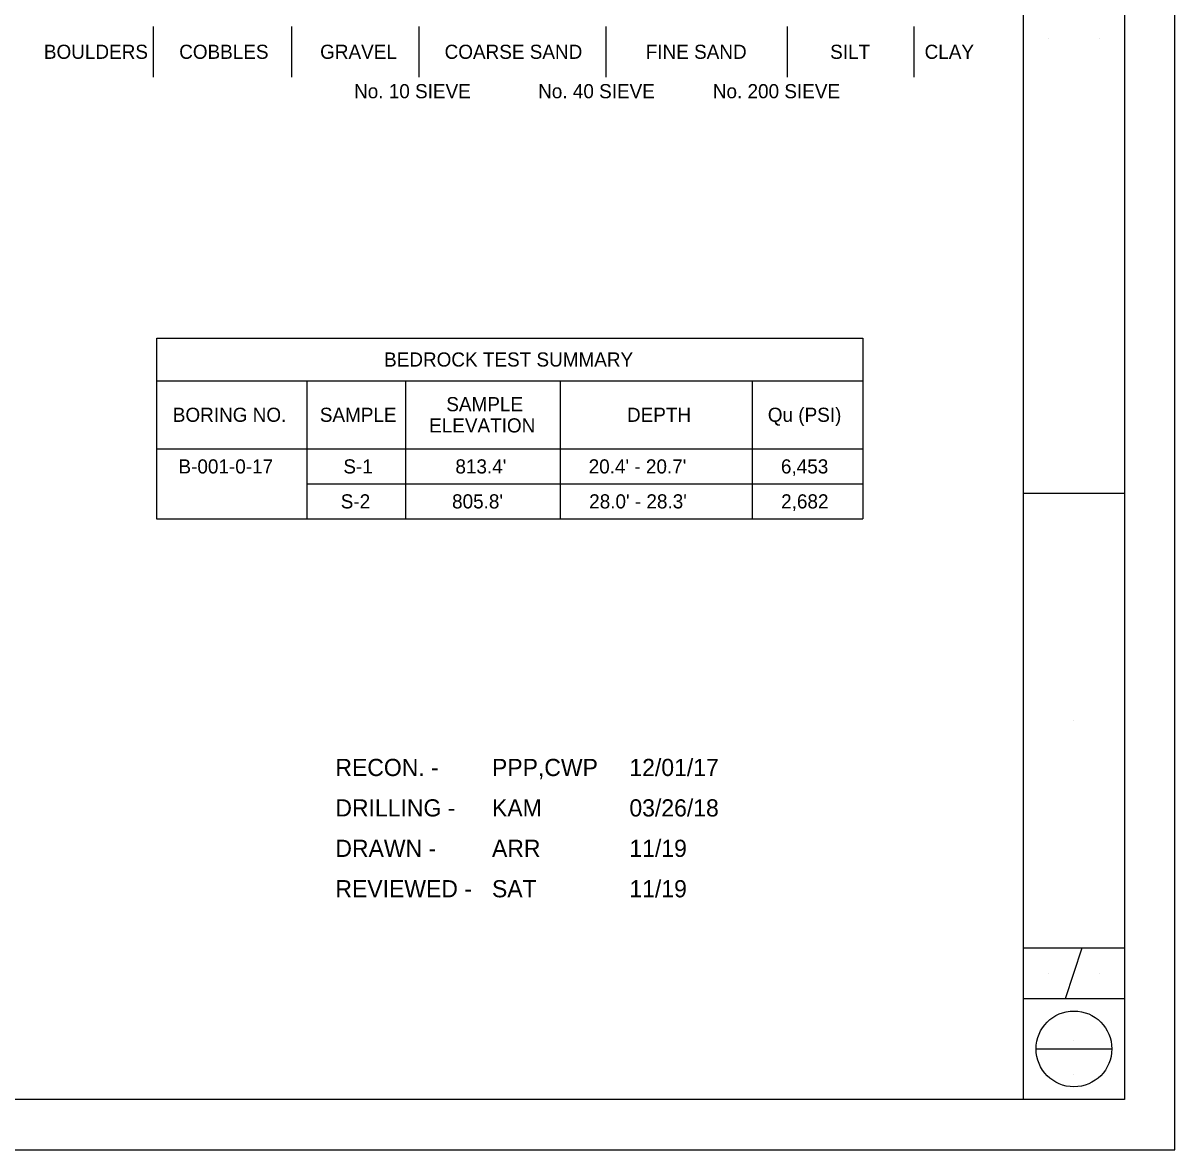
# Model space of a CAD drawing. Extents: x 0 to 34, y 0 to 22.
# Drawn here: x 22.6 to 34, y 0 to 11.15 of the extents above; entities that cross this region are included whole.
import ezdxf

# ---------------------------------------------------------------- set-up
doc = ezdxf.new("R2010")
doc.units = 0
for name, color, linetype in [('SH_Border', 7, 'Continuous'), ('SH_Cut_Line', 7, 'Continuous'), ('SH_Data', 7, 'Continuous'), ('SH_Text', 7, 'Continuous')]:
    doc.layers.add(name, color=color, linetype=linetype)

msp = doc.modelspace()

# ---------------------------------------------------------------- linework, layer by layer
at = {"layer": 'SH_Border'}
for p, q in [((32.5, 0.5), (32.5, 21.5)), ((32.5, 6.5), (33.5, 6.5)), ((32.5, 2), (33.5, 2)), ((32.917, 1.5), (33.083, 2)), ((32.5, 1.5), (33.5, 1.5))]:
    msp.add_line(p, q, dxfattribs=at)
msp.add_lwpolyline([(2, 21.5), (33.5, 21.5), (33.5, 0.5), (2, 0.5)], close=True, dxfattribs=at)
at = {"layer": 'SH_Cut_Line'}
msp.add_lwpolyline([(0, 0), (34, 0), (34, 22), (0, 22)], close=True, dxfattribs=at)
at = {"layer": 'SH_Data'}
for p, q in [((32.75, 11), (32.75, 11)), ((33.25, 11), (33.25, 11)), ((23.921, 8.032), (23.921, 6.245)), ((23.922, 8.032), (30.911, 8.032)), ((30.911, 8.032), (30.911, 6.245)), ((23.922, 7.612), (30.911, 7.612)), ((25.411, 6.245), (25.411, 7.612)), ((26.387, 6.245), (26.387, 7.612)), ((27.917, 6.245), (27.917, 7.612)), ((29.82, 6.245), (29.82, 7.612)), ((23.922, 6.937), (30.911, 6.937)), ((25.411, 6.591), (30.911, 6.591)), ((23.919, 6.245), (30.911, 6.245)), ((33, 4.25), (33, 4.25)), ((32.75, 1.75), (32.75, 1.75)), ((33.25, 1.75), (33.25, 1.75)), ((33, 1.085), (33, 1.085)), ((32.625, 1), (33.375, 1)), ((33, 0.745), (33, 0.745))]:
    msp.add_line(p, q, dxfattribs=at)
msp.add_circle((33, 1), 0.375, dxfattribs=at)
at = {"layer": 'SH_Text'}
for p, q in [((23.89, 10.617), (23.89, 11.117)), ((25.26, 10.617), (25.26, 11.117)), ((26.52, 10.617), (26.52, 11.117)), ((28.37, 10.617), (28.37, 11.117)), ((30.165, 10.617), (30.165, 11.117)), ((31.419, 10.617), (31.419, 11.117))]:
    msp.add_line(p, q, dxfattribs=at)

# ---------------------------------------------------------------- texts
for s, height, p in [('BOULDERS', 0.14, (22.805, 10.797)), ('COBBLES', 0.14, (24.144, 10.797)), ('GRAVEL', 0.14, (25.539, 10.797)), ('COARSE SAND', 0.14, (26.771, 10.797)), ('FINE SAND', 0.14, (28.762, 10.797)), ('SILT', 0.14, (30.587, 10.797)), ('CLAY', 0.14, (31.522, 10.797)), ('No. 10 SIEVE', 0.14, (25.875, 10.407)), ('No. 40 SIEVE', 0.14, (27.697, 10.407)), ('No. 200 SIEVE', 0.14, (29.426, 10.407)), ('BEDROCK TEST SUMMARY', 0.14, (26.172, 7.752)), ('SAMPLE', 0.14, (26.788, 7.31)), ('BORING NO.', 0.14, (24.081, 7.205)), ('SAMPLE', 0.14, (25.536, 7.205)), ('DEPTH', 0.14, (28.576, 7.205)), ('Qu (PSI)', 0.14, (29.97, 7.205)), ('ELEVATION', 0.14, (26.618, 7.1)), ('B-001-0-17', 0.14, (24.137, 6.694)), ('S-1', 0.14, (25.769, 6.694)), ("813.4'", 0.14, (26.878, 6.694)), ("20.4' - 20.7'", 0.14, (28.197, 6.694)), ('6,453', 0.14, (30.1, 6.694)), ('S-2', 0.14, (25.743, 6.348)), ("805.8'", 0.14, (26.845, 6.348)), ("28.0' - 28.3'", 0.14, (28.202, 6.348)), ('2,682', 0.14, (30.102, 6.348)), ('12/01/17', 0.17, (28.6, 3.7)), ('RECON. -', 0.17, (25.69, 3.7)), ('PPP,CWP', 0.17, (27.24, 3.7)), ('DRILLING -', 0.17, (25.69, 3.3)), ('KAM', 0.17, (27.24, 3.3)), ('03/26/18', 0.17, (28.6, 3.3)), ('11/19', 0.17, (28.6, 2.9)), ('DRAWN -', 0.17, (25.69, 2.9)), ('ARR', 0.17, (27.24, 2.9)), ('REVIEWED -', 0.17, (25.69, 2.5)), ('SAT', 0.17, (27.24, 2.5)), ('11/19', 0.17, (28.6, 2.5))]:
    msp.add_text(s, height=height, dxfattribs=at).set_placement(p)

doc.saveas('drawing.dxf')
